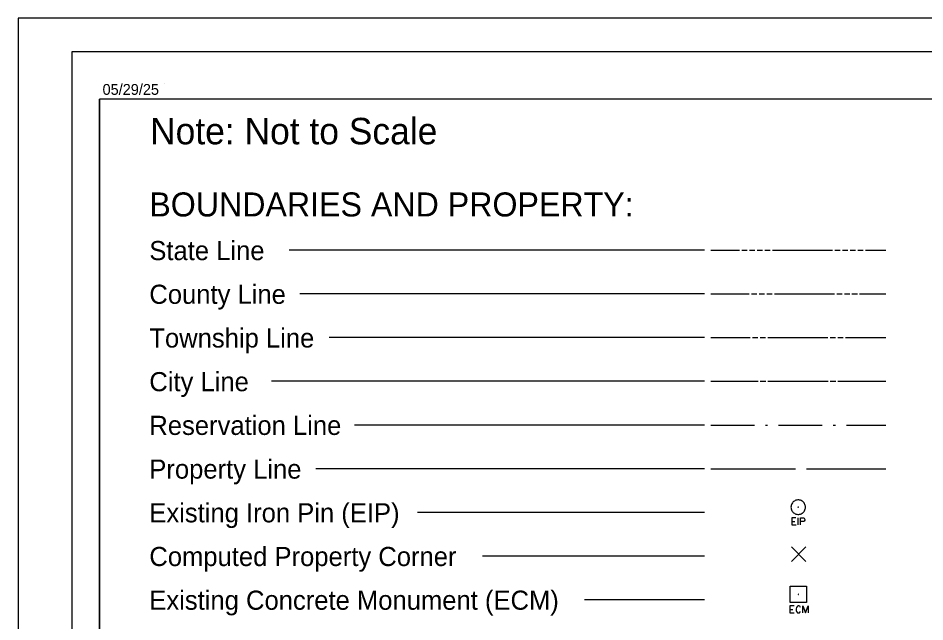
# Model space of a CAD drawing. Extents: x 811508 to 813252, y 647626 to 648754.
# Drawn here: x 811508.1 to 811937.3, y 648468 to 648754 of the extents above; entities that cross this region are included whole.
import ezdxf

# ---------------------------------------------------------------- set-up
doc = ezdxf.new("R2010")
doc.units = 0
for name, color, linetype in [('Sheet Cutting Line CELL', 7, 'Continuous'), ('Sheet Plot Border Inside CELL', 7, 'Continuous'), ('Sheet Plot Border Outside CELL', 7, 'Continuous'), ('Sheet_Plan', 7, 'Continuous'), ('Sheet_Symbology', 7, 'Continuous'), ('z - Construction', 7, 'Continuous')]:
    doc.layers.add(name, color=color, linetype=linetype)

msp = doc.modelspace()

# ---------------------------------------------------------------- linework, layer by layer
at = {"layer": 'Sheet Cutting Line CELL'}
for p, q in [((813217.6, 648737.99), (811533.6, 648737.99)), ((811533.6, 648737.99), (811533.6, 647637.99))]:
    msp.add_line(p, q, dxfattribs=at)
at = {"layer": 'Sheet Plot Border Inside CELL'}
msp.add_lwpolyline([(811546.6, 647660.44), (813213.1, 647660.44), (813213.1, 648715.54), (811546.6, 648715.54)], close=True, dxfattribs=at)
at = {"layer": 'Sheet Plot Border Outside CELL'}
msp.add_lwpolyline([(811533.6, 647637.99), (813217.6, 647637.99), (813217.6, 648737.99), (811533.6, 648737.99)], close=True, dxfattribs=at)
at = {"layer": 'Sheet_Plan'}
for p, q in [((811577.34, 648723.26), (811577.34, 648723.26)), ((811546.61, 647664.09), (811546.6, 648715.54)), ((813213.53, 648715.54), (811546.6, 648715.54))]:
    msp.add_line(p, q, dxfattribs=at)
at = {"layer": 'Sheet_Symbology'}
for p, q in [((811832.99, 648644.07), (811636.36, 648644.07)), ((811835.96, 648644.07), (811849.62, 648644.07)), ((811850.66, 648644.07), (811853.25, 648644.07)), ((811854.28, 648644.07), (811856.87, 648644.07)), ((811857.9, 648644.07), (811860.49, 648644.07)), ((811861.53, 648644.07), (811864.11, 648644.07)), ((811865.15, 648644.07), (811893.61, 648644.07)), ((811894.65, 648644.07), (811897.23, 648644.07)), ((811898.27, 648644.07), (811900.86, 648644.07)), ((811901.89, 648644.07), (811904.48, 648644.07)), ((811905.51, 648644.07), (811908.1, 648644.07)), ((811909.13, 648644.07), (811918.76, 648644.07)), ((811832.99, 648623.37), (811641.52, 648623.37)), ((811835.96, 648623.37), (811854.17, 648623.37)), ((811855.2, 648623.37), (811857.79, 648623.37)), ((811858.82, 648623.37), (811861.41, 648623.37)), ((811862.44, 648623.37), (811865.03, 648623.37)), ((811866.07, 648623.37), (811894.53, 648623.37)), ((811895.56, 648623.37), (811898.15, 648623.37)), ((811899.19, 648623.37), (811901.77, 648623.37)), ((811902.81, 648623.37), (811905.4, 648623.37)), ((811906.43, 648623.37), (811918.76, 648623.37)), ((811832.99, 648602.67), (811655.28, 648602.67)), ((811835.96, 648602.67), (811854.64, 648602.67)), ((811855.68, 648602.67), (811858.27, 648602.67)), ((811859.3, 648602.67), (811861.89, 648602.67)), ((811862.92, 648602.67), (811891.39, 648602.67)), ((811892.42, 648602.67), (811895.01, 648602.67)), ((811896.04, 648602.67), (811898.63, 648602.67)), ((811899.66, 648602.67), (811918.76, 648602.67)), ((811832.99, 648581.97), (811627.99, 648581.97)), ((811835.96, 648581.97), (811858.36, 648581.97)), ((811859.39, 648581.97), (811861.98, 648581.97)), ((811863.01, 648581.97), (811891.48, 648581.97)), ((811892.51, 648581.97), (811895.1, 648581.97)), ((811896.13, 648581.97), (811918.76, 648581.97)), ((811832.99, 648561.27), (811667.31, 648561.27)), ((811835.96, 648561.27), (811856.66, 648561.27)), ((811861.84, 648561.27), (811862.87, 648561.27)), ((811868.05, 648561.27), (811888.75, 648561.27)), ((811893.92, 648561.27), (811894.96, 648561.27)), ((811900.13, 648561.27), (811918.76, 648561.27)), ((811832.99, 648540.58), (811649.11, 648540.58)), ((811835.96, 648540.58), (811876.07, 648540.58)), ((811881.24, 648540.58), (811918.76, 648540.58)), ((811832.99, 648519.88), (811697.11, 648519.88)), ((811874.4, 648515.59), (811875.75, 648515.59)), ((811877.37, 648513.93), (811877.37, 648517.24)), ((811881, 648496.67), (811874.16, 648503.51)), ((811874.16, 648496.67), (811881, 648503.51)), ((811832.99, 648499.18), (811728, 648499.18)), ((811832.99, 648478.48), (811776.24, 648478.48)), ((811873.45, 648473.92), (811874.81, 648473.92))]:
    msp.add_line(p, q, dxfattribs=at)
for points in [[(811880.77, 648522.36), (811880.74, 648522.8), (811880.66, 648523.21), (811880.52, 648523.63), (811880.36, 648524.01), (811880.11, 648524.37), (811879.84, 648524.7), (811879.53, 648525), (811879.18, 648525.25), (811878.82, 648525.47), (811878.41, 648525.61), (811877.99, 648525.72), (811877.58, 648525.77), (811877.14, 648525.77), (811876.7, 648525.72), (811876.29, 648525.61), (811875.9, 648525.47), (811875.52, 648525.25), (811875.16, 648525), (811874.86, 648524.7), (811874.58, 648524.37), (811874.36, 648524.01), (811874.17, 648523.63), (811874.03, 648523.21), (811873.95, 648522.8), (811873.92, 648522.36), (811873.95, 648521.92), (811874.03, 648521.51), (811874.17, 648521.09), (811874.36, 648520.71), (811874.58, 648520.35), (811874.86, 648520.02), (811875.16, 648519.72), (811875.52, 648519.47), (811875.9, 648519.25), (811876.29, 648519.11), (811876.7, 648519), (811877.14, 648518.95), (811877.58, 648518.95), (811877.99, 648519), (811878.41, 648519.11), (811878.82, 648519.25), (811879.18, 648519.47), (811879.53, 648519.72), (811879.84, 648520.02), (811880.11, 648520.35), (811880.36, 648520.71), (811880.52, 648521.09), (811880.66, 648521.51), (811880.74, 648521.92), (811880.77, 648522.36)], [(811877.42, 648522.44), (811877.33, 648522.47), (811877.28, 648522.42), (811877.25, 648522.33), (811877.31, 648522.28), (811877.39, 648522.25), (811877.44, 648522.3), (811877.47, 648522.39), (811877.42, 648522.44)], [(811876.3, 648517.24), (811874.4, 648517.24), (811874.4, 648513.93), (811876.43, 648513.93)], [(811878.47, 648513.93), (811878.47, 648517.24), (811879.8, 648517.24), (811880.19, 648517.11), (811880.53, 648516.58), (811880.53, 648516.27), (811880.21, 648515.75), (811879.8, 648515.62), (811878.47, 648515.62)], [(811873.48, 648484.99), (811881.23, 648484.99), (811881.23, 648477.23), (811873.48, 648477.23), (811873.48, 648484.99)], [(811877.34, 648481.21), (811877.3, 648481.17), (811877.3, 648481.09), (811877.37, 648481.01), (811877.45, 648481.05), (811877.49, 648481.13), (811877.41, 648481.21), (811877.34, 648481.21)], [(811875.36, 648475.57), (811873.45, 648475.57), (811873.45, 648472.25), (811875.49, 648472.25)], [(811878.49, 648474.91), (811878.07, 648475.46), (811877.65, 648475.57), (811877.37, 648475.57), (811876.97, 648475.46), (811876.53, 648474.91), (811876.43, 648474.18), (811876.43, 648473.79), (811876.43, 648473.53), (811876.45, 648473.3), (811876.53, 648472.88), (811876.97, 648472.36), (811877.37, 648472.25), (811877.6, 648472.25), (811878.04, 648472.36), (811878.49, 648472.88)], [(811879.56, 648472.25), (811879.56, 648475.57), (811880.81, 648472.25), (811882.01, 648475.57), (811882.01, 648472.25)]]:
    msp.add_lwpolyline(points, dxfattribs=at)
at = {"layer": 'z - Construction'}
for p, q in [((813251.99, 648754), (811508.14, 648754)), ((811508.14, 648754), (811508.14, 647625.63))]:
    msp.add_line(p, q, dxfattribs=at)

# ---------------------------------------------------------------- texts
at = {"layer": 'Sheet_Plan'}
msp.add_text('05/29/25', height=5.129, rotation=0, dxfattribs=at).set_placement((811548.1, 648717.66))
at = {"layer": 'Sheet_Symbology'}
msp.add_text('Note: Not to Scale', height=12.5309, rotation=360, dxfattribs=at).set_placement((811570.58, 648694.23))
for s, height, p in [('BOUNDARIES AND PROPERTY:', 11.3847, (811570.22, 648660.06)), ('State Line', 9.056, (811570.23, 648639.38)), ('County Line', 9.056, (811570.23, 648618.68)), ('Township Line', 9.056, (811570.23, 648597.98)), ('City Line', 9.056, (811570.23, 648577.28)), ('Reservation Line', 9.056, (811570.23, 648556.58)), ('Property Line', 9.056, (811570.23, 648535.88)), ('Existing Iron Pin (EIP)', 9.056, (811570.23, 648515.18)), ('Computed Property Corner', 9.056, (811570.23, 648494.48)), ('Existing Concrete Monument (ECM)', 9.056, (811570.23, 648473.78))]:
    msp.add_text(s, height=height, dxfattribs=at).set_placement(p)

doc.saveas('drawing.dxf')
